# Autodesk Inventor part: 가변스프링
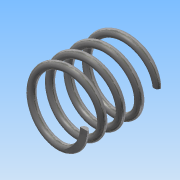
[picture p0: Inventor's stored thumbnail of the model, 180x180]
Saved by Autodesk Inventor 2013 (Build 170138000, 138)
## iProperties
Created: 2017-07
Part Number: 가변스프링
Material: 스테인리스강, 440C
Document SubType Name: Modeling
Designer: Administrator
Density: 7.75 g/cm^3
Mass: 5.09233 g
Surface Area: 13.3836 cm^2
Volume: 0.657075 cm^3
Author: Administrator
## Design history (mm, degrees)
sketch "스케치1"
  geometry: L1 (8.5, 0)-(0, 0); L2 (0, 0)-(0, 20.5); L3 (0, 20.5)-(8.5, 20.5); C1 r 1 at (8.5, 0)
  constraints: 6 end point, 1 centre point, 1 horizontal, 1 horizontal alignment, 1 parallel, 1 perpendicular
  dimensions: "d0" = 2 diameter of C1; "d1" = 8.5 distance of L1.start L1.end; "d2" = 8.5 distance of L2.end L3.end; "d3" = 20.5 distance of L1.end L2.end (derived)
feature "코일2" sketch "스케치1" pitch "d17" = 10; turns "d19" = 4; dims "d18" = 20.5 (= d3), "d20" = 0, angle "d21" = 90 deg, angle "d22" = 90 deg, "d23" = 0, "d24" = 0
sketch "스케치3"
  geometry: L1 (0, 15)-(20.5, 15); L2 (20.5, 15)-(20.5, -15); L3 (20.5, -15)-(0, -15); L4 (0, -15)-(0, 15); 2 further points
  constraints: 8 end point, 2 parallel, 1 coincident, 1 horizontal, 1 midpoint, 1 perpendicular
  dimensions: "d25" = 30 distance of L1.end L2.end; "d27" = 20.5 distance of L1.start L1.end (derived)
extrude "돌출2" sketch "스케치3" stored distance "d28" = 30; taper "d29" = 0 deg
node "솔리드2"
